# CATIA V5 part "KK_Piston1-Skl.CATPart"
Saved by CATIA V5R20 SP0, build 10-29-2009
Part number: Piston1-Skl
Publications: "Point.1"
Bounding box of the stored display mesh (mm): x -50.294 to -20, y 61.535 to 86.432, z 0 to 100
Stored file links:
  G:\Khaled_CFAO_2011\ST2M\ST2M_GR1\msallin\Khaled\Version_Finale\KK_Piston1-Skl.CATPart
  C:\Users\Mathieu\Desktop\Think Motion\JOUG-MELEE2.CATProduct
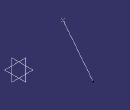
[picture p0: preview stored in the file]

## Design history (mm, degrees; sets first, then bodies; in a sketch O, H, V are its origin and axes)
External parameters (linked from other documents)
  `External.Taille du joug` = 100 mm
Set1
  Point1: linked copy from another document
  Point2: linked copy from another document
Set2
  Line1: type PtPt, FirstPoint Point1, SecondPoint Point2
  Point3: (0, 0, 0), relative to Point1
Body1 (main body)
